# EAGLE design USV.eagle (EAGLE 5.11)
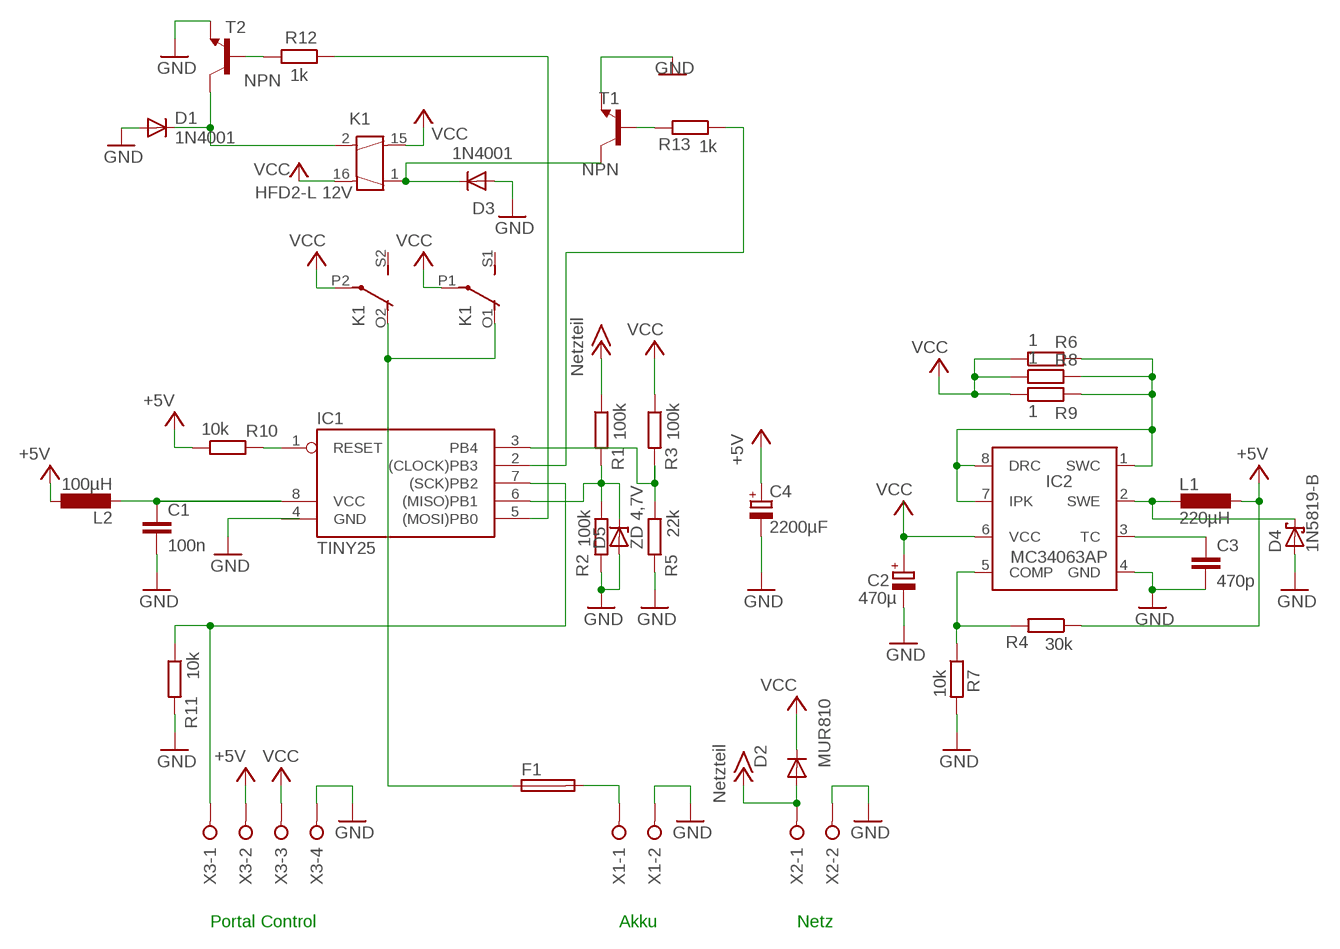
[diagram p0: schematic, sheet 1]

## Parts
C1  100n  C-EU025-025X050  [C025-025X050]
C2  470µ  CPOL-EUE5-10.5  [E5-10,5]
C3  470p  C-EU025-025X050  [C025-025X050]
C4  2200µF  CPOL-EUE5-13  [E5-13]
D1  1N4001  1N4004  [DO41-10]
D2  MUR810  [TO220ACS]
D3  1N4001  1N4004  [DO41-10]
D4  1N5819-B  [DO41-7.6]
D5  ZD 4,7V  ZENER-DIODEZD-2.5  [ZDIO-2.5]
F1  FUSEKS9V  [KS9V]
IC1  TINY25  TINY22P  [DIL08]
IC2  MC34063AP  [DIL-08]
K1  HFD2-L 12V  DS2-L2-12V  [DS2E-L2]
L1  220µH  L-EU6000-XXX-RC  [6000-XXXX-RC]
L2  100µH  L-EU0207/7  [0207/7]
R1  100k  R-EU_0207/10  [0207/10]
R2  100k  R-EU_0207/10  [0207/10]
R3  100k  R-EU_0207/10  [0207/10]
R4  30k  R-EU_0207/10  [0207/10]
R5  22k  R-EU_0207/10  [0207/10]
R6  1  R-EU_0207/10  [0207/10]
R7  10k  R-EU_0207/10  [0207/10]
R8  1  R-EU_0207/10  [0207/10]
R9  1  R-EU_0207/10  [0207/10]
R10  10k  R-EU_0207/7  [0207/7]
R11  10k  R-EU_0207/2V  [0207/2V]
R12  1k  R-EU_0207/2V  [0207/2V]
R13  1k  R-EU_0207/10  [0207/10]
T1  NPN  BC337-16-NPN-TO92-CBE  [TO92-CBE]
T2  NPN  BC337-16-NPN-TO92-CBE  [TO92-CBE]
X1  W237-02P  [W237-132]
X2  W237-02P  [W237-132]
X3  W237-04P  [W237-4P]

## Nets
+5V: C4.+ L1.1 L2.1 R4.1 R10.1 X3.2
+15V: D2.A R1.1 X2.1 ; supply symbol labelled Netzteil
GND: C1.2 C2.- C3.2 C4.- D1.A D3.A D4.A D5.A IC2.4(GND) R2.2 R5.2 R7.2 R11.2 T1.E T2.E X1.2 X2.2 X3.4
N$1: F1.1 K1.O1(2:O) K1.O2(3:O)
N$2: D5.C IC1.6((MISO)PB1) R1.2 R2.1
N$3: IC1.5((MOSI)PB0) R12.1
N$4: IC1.3(PB4) R3.2 R5.1
N$5: D4.C IC2.2(SWE) L1.2
N$6: IC2.1(SWC) IC2.7(IPK) IC2.8(DRC) R6.2 R8.2 R9.2
N$7: IC1.7((SCK)PB2) R11.1 X3.1
N$8: IC1.2((CLOCK)PB3) R13.1
N$9: IC2.5(COMP) R4.2 R7.1
N$10: F1.2 X1.1
N$11: C3.1 IC2.3(TC)
N$12: D1.C K1.2 T2.C
N$13: C1.1 IC1.8(VCC) L2.2
N$14: IC1.1(RESET) R10.2
N$18: D3.C K1.1 T1.C
N$19: R12.2 T2.B
N$20: R13.2 T1.B
VCC: C2.+ D2.C IC2.6(VCC) K1.15 K1.16 K1.P1(2:P) K1.P2(3:P) R3.1 R6.1 R8.1 R9.1 X3.3
Unconnected: K1.S1(2:S) K1.S2(3:S)

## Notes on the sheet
- Portal Control | Akku | Netz

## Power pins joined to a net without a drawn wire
GND: IC1.4(GND)

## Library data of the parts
C1 C3 = rcl:C-EU: CAPACITOR, European symbol
C2 C4 = rcl:CPOL-EU: POLARIZED CAPACITOR, European symbol
D1 D3 = diode:1N4004: DIODE
D2 = diode:MUR810: DIODE
D4 = diode:1N581*: 1.0A SCHOTTKY BARRIER RECTIFIER
D5 = diode:ZENER-DIODE: Z-Diode
F1 = fuse:FUSE: Fuse; OC_FARNELL: unknown; OC_NEWARK: unknown
IC1 = avr-7:TINY22: MICROCONTROLLER 1K ROM 128 bytes RAM 128 bytes EEPROM
IC2 = v-reg-3:MC34063A: 1.5A Step-Up/Down/Inverting Switching Regulator NPN Darlington Switch, Vin 3V to 40V, Current Limiter Input, adjustable Frequency up to 100kHz
K1 = relay:DS2-L2-*: RELAY NAiS bistable, 2 x switch, 4 A/250 V; OC_FARNELL: unknown; OC_NEWARK: unknown
L1 L2 = rcl:L-EU: INDUCTOR, European symbol
R1-R13 = rcl:R-EU_: RESISTOR, European symbol
T1 T2 = transistor:*-NPN-: NPN Transistror BF959 corrected 2008.03.06
X1 X2 = con-wago-508:W237-02P: WAGO SREW CLAMP; OC_FARNELL: unknown; OC_NEWARK: unknown
X3 = con-wago-508:W237-04P: WAGO SREW CLAMP; OC_FARNELL: unknown; OC_NEWARK: unknown

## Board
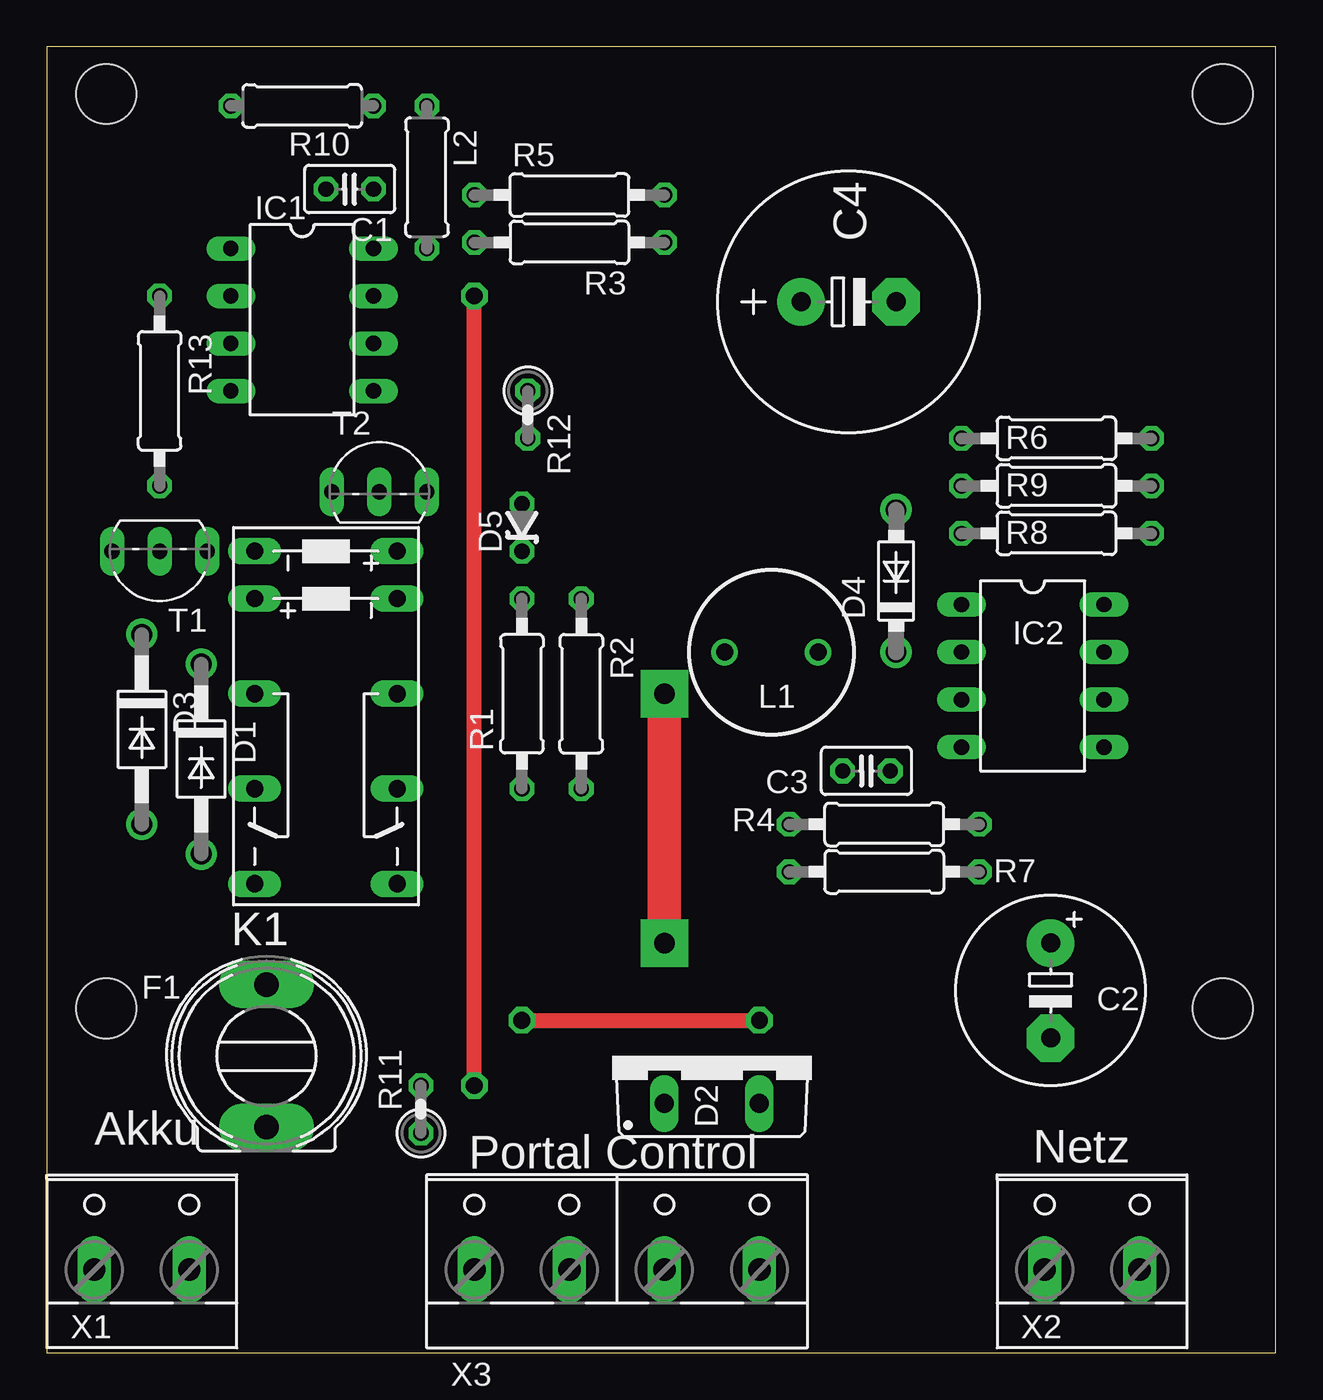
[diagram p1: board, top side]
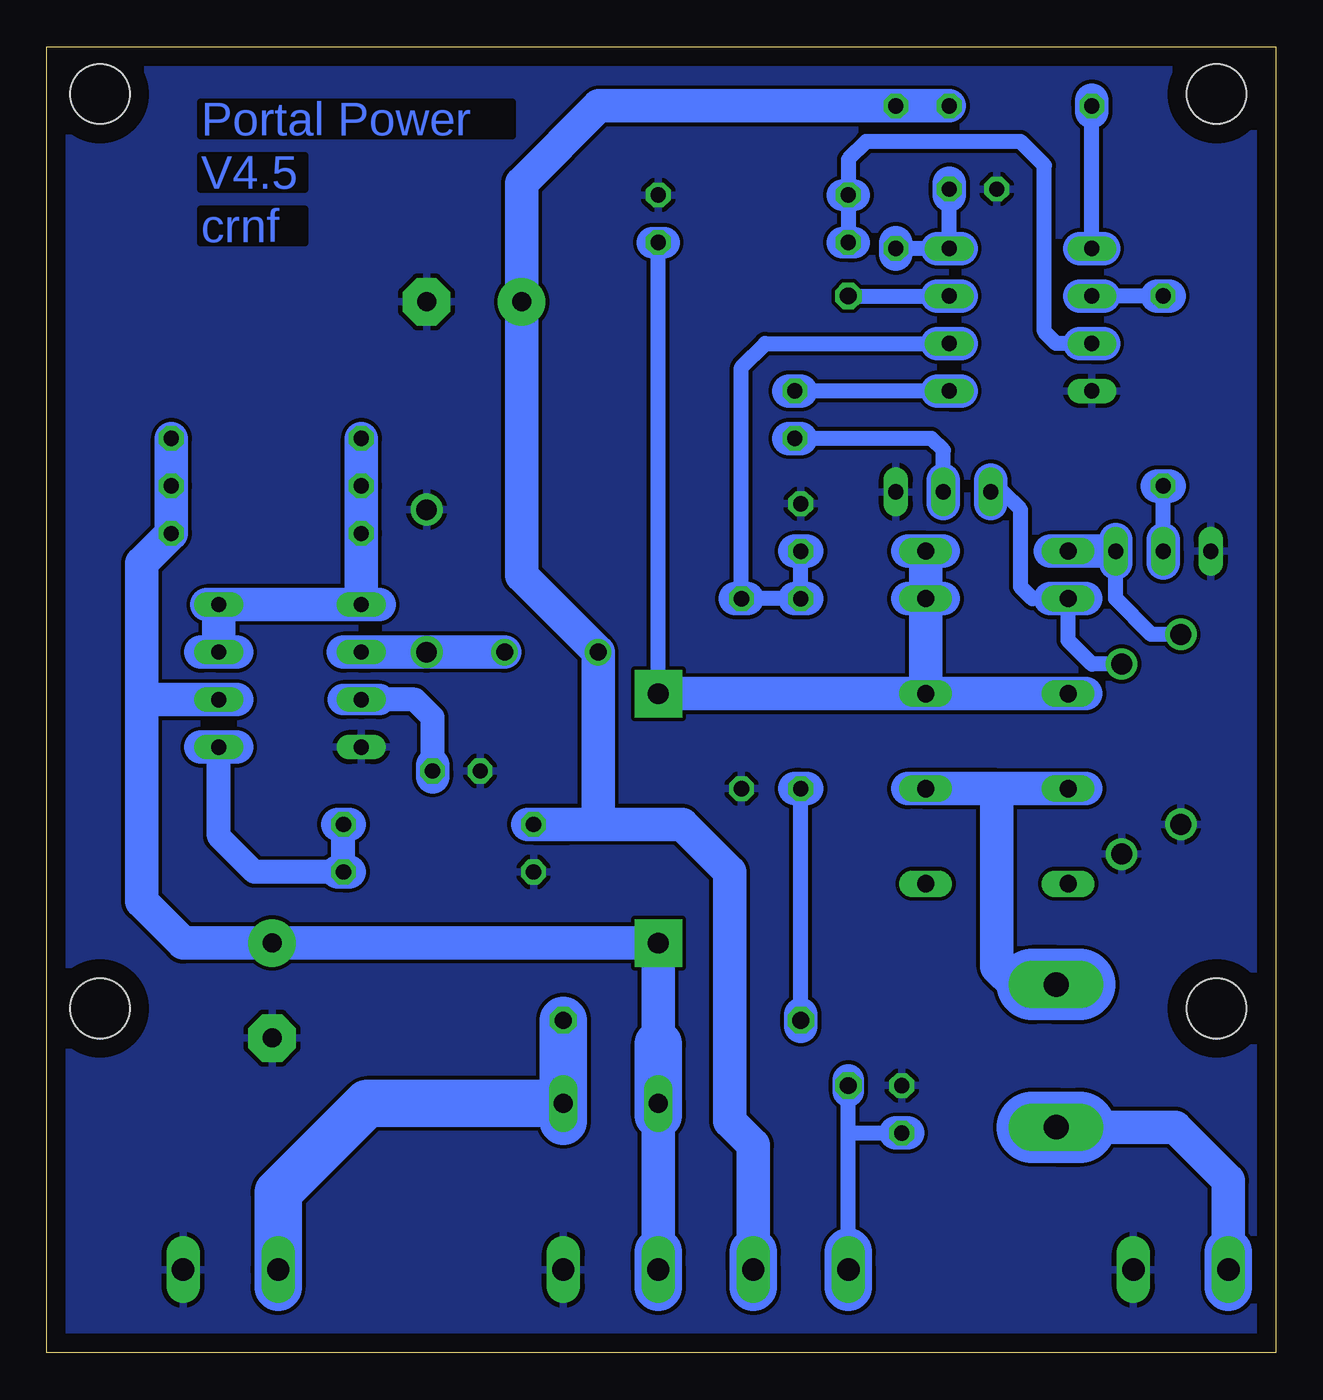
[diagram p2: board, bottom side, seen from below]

Size 65.71 x 69.84 mm. Coordinates in mm from the lower left corner, seen from the top.
Outline: 0,0 65.71,0 65.71,69.84 0,69.84 0,0
Copper layers (1*16): Top 0.035mm / dielectric 1.5mm / Bottom 0.035mm
Design rules "default": minimum track width 10mil, minimum drill 24mil, track to track 8mil, track to pad 8mil, pad to pad 8mil, via to via 8mil, smd to smd 8mil, copper to edge 40mil, drill to drill 8mil, minimum pad ring 10mil, minimum via ring 8mil, stop-mask expansion 4mil, vias tented up to drill 0mil, thermal gap 10mil
Holes 3.2 mm at 3.17,18.41 62.87,18.41 3.17,67.31 62.87,67.31

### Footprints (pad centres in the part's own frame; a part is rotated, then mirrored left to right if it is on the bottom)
C025-025X050 = drill 0.813 octagon: 1 -1.27,0; 2 1.27,0
E5-10,5 = drill 1.016 pad 2.54 round: + -2.54,0 | drill 1.016 pad 2.54 octagon: - 2.54,0
E5-13 = drill 1.016 pad 2.54 round: + -2.54,0 | drill 1.016 pad 2.54 octagon: - 2.54,0
DO41-10 = drill 1.118 round: A 5.08,0; C -5.08,0
TO220ACS = drill 1.016 long: A 2.54,-2.54; C -2.54,-2.54
DO41-7.6 = drill 1.1 pad 1.7 round: A 3.81,0; C -3.81,0
ZDIO-2.5 = drill 0.813 octagon: A 1.27,0; C -1.27,0
KS9V = drill 1.321 pad 2.54 long: 1 0,3.81; 2 0,-3.81
DIL08 = drill 0.813 long: 1 -3.81,-3.81; 2 -1.27,-3.81; 3 1.27,-3.81; 4 3.81,-3.81; 5 3.81,3.81; 6 1.27,3.81; 7 -1.27,3.81; 8 -3.81,3.81
DIL-08 = drill 0.813 long: 1 -3.81,-3.81; 2 -1.27,-3.81; 3 1.27,-3.81; 4 3.81,-3.81; 5 3.81,3.81; 6 1.27,3.81; 7 -1.27,3.81; 8 -3.81,3.81
DS2E-L2 = drill 0.914 long: 1 -7.62,-3.81; 2 -5.08,-3.81; 15 -5.08,3.81; 16 -7.62,3.81; O1 5.08,-3.81; O2 5.08,3.81; P1 0,-3.81; P2 0,3.81; S1 10.16,-3.81; S2 10.16,3.81
6000-XXXX-RC = drill 0.9 pad 1.422 round: 1 -2.5,0; 2 2.5,0
0207/7 = drill 0.813 octagon: 1 -3.81,0; 2 3.81,0
0207/10 = drill 0.813 octagon: 1 -5.08,0; 2 5.08,0
0207/2V = drill 0.813 octagon: 1 -1.27,0; 2 1.27,0
TO92-CBE = drill 0.813 long: B 0,0; C -2.54,0; E 2.54,0
W237-132 = drill 1.194 long: 1 -2.54,-0.635; 2 2.54,-0.635
W237-4P = drill 1.194 long: 1 -7.62,-0.635; 2 -2.54,-0.635; 3 2.54,-0.635; 4 7.62,-0.635

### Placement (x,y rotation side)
C1  16.19,62.23 180 top
C2  53.66,19.37 270 top
C3  43.81,31.11 180 top
C4  42.86,56.2 0 top
D1  8.26,31.75 270 top
D2  35.56,15.88 0 top
D3  5.08,33.34 270 top
D4  45.4,41.27 90 top
D5  25.4,44.13 90 top
F1  11.75,15.88 0 top
IC1  13.65,55.24 270 top
IC2  52.7,36.2 270 top
K1  14.92,35.24 270 top
L1  38.73,37.47 0 top
L2  20.32,62.87 270 top
R1  25.4,35.24 90 top
R2  28.57,35.24 270 top
R3  27.94,59.37 180 top
R4  44.77,28.26 0 top
R5  27.94,61.91 0 top
R6  53.98,48.9 180 top
R7  44.77,25.72 180 top
R8  53.98,43.81 180 top
R9  53.98,46.35 180 top
R10  13.65,66.67 180 top
R11  20,13.02 90 top
R12  25.72,50.16 270 top
R13  6.03,51.44 270 top
T1  6.03,42.86 180 top
T2  17.78,46.04 0 top
X1  5.08,5.08 0 top
X2  55.88,5.08 0 top
X3  30.48,5.08 0 top

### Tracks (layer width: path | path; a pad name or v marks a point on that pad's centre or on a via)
+5V
  Bottom 1.778: 37.78,28.26 R4.1 36.2,28.26 | R10.1 L2.1 36.2,66.67 40.32,62.55 C4.+ 40.32,41.55 L1.1 36.23,28.3 36.2,28.26 | 36.2,28.26 31.75,28.26 29.21,25.72 29.21,12.38 27.94,11.11 27.94,5.4
  Bottom 2.54: 27.94,5.4 X3.2 27.94,3.49
+15V  (via drill 0.9 pad 1.42)
  Top 0.813: v25.4,17.78 v38.1,17.78
  Bottom 0.813: v25.4,17.78 R1.1
  Bottom 1.676: 38.1,18.1 v38.1,17.78 38.1,17.46
  Bottom 1.778: 25.4,18.1 v25.4,17.78 25.4,17.46 | 25.72,30.16 R1.1 25.08,30.16
  Bottom 2.54: 38.1,17.46 v38.1,17.78 D2.A | D2.A 38.1,12.38 | D2.A 48.58,13.34 53.34,8.57 X2.1 53.34,3.49
GND
  pour Bottom: 0,0 0,69.85 66.04,69.85 66.04,0
N$1
  Bottom 1.778: 13.02,19.68 13.97,19.68 14.92,20.64 14.92,30.16 K1.O2 | K1.O2 19.68,30.16 | K1.O2 K1.O1 10.16,30.16
  Bottom 3.81: 10.48,19.68 F1.1 13.02,19.68
N$2
  Bottom 0.813: 18.1,53.98 27.3,53.98 28.57,52.7 R2.1 28.26,40.32 25.72,40.32 | R1.2 D5.C
  Bottom 1.778: 16.83,53.98 IC1.6 18.1,53.98 | 25.72,42.86 D5.C 25.08,42.86 | 25.72,40.32 R1.2 25.08,40.32 | 28.89,40.32 R2.1 28.26,40.32
N$3
  Bottom 0.813: 18.1,51.44 25.4,51.44
  Bottom 1.778: 16.83,51.44 IC1.5 18.1,51.44 | 26.04,51.44 R12.1 25.4,51.44
N$4
  Bottom 0.813: R3.2 R5.1 22.86,63.82 21.91,64.77 13.65,64.77 12.38,63.5 12.38,54.61 11.75,53.98 10.48,53.98
  Bottom 1.676: 23.18,61.91 R5.1 22.54,61.91 | 23.18,59.37 R3.2 22.54,59.37
  Bottom 1.778: 10.48,53.98 IC1.3 9.21,53.98
N$5
  Bottom 1.778: IC2.2 48.58,37.47 | IC2.2 49.85,37.47 | L1.2 D4.C IC2.2
N$6
  Bottom 1.778: IC2.1 R8.2 R9.2 R6.2 | IC2.1 IC2.8 | IC2.8 57.15,40.01 | IC2.7 55.56,37.47 | IC2.7 57.47,37.47 | IC2.8 IC2.7 | 47.94,40.01 IC2.1
N$7  (via drill 0.9 pad 1.42)
  Top 0.813: v22.86,14.29 v22.86,56.52
  Bottom 0.813: 22.86,5.4 22.86,11.75 | 22.86,11.75 22.86,13.97 | 22.86,11.75 20.32,11.75 | v22.86,56.52 18.1,56.52
  Bottom 1.676: 22.86,14.61 v22.86,14.29 22.86,13.97
  Bottom 1.778: 18.1,56.52 IC1.7 16.83,56.52 | 20.32,11.75 R11.1 19.68,11.75
  Bottom 2.54: 22.86,5.4 X3.1 22.86,3.49
N$8
  Bottom 0.813: 5.71,56.52 IC1.2
  Bottom 1.778: 10.48,56.52 IC1.2 9.21,56.52 | 6.35,56.52 R13.1 5.71,56.52
N$9
  Bottom 1.27: IC2.5 56.52,27.62 54.61,25.72 50.16,25.72 | R7.1 R4.2
  Bottom 1.778: 50.16,28.26 R4.2 49.53,28.26 | 50.16,25.72 R7.1 49.53,25.72
N$10
  Bottom 1.778: F1.2 5.4,12.06 2.54,9.21 2.54,5.4
  Bottom 2.54: 2.54,5.4 X1.1 2.54,3.49
  Bottom 3.81: 13.02,12.06 F1.2 10.48,12.06
N$11
  Bottom 1.27: 47.94,34.92 46.04,34.92 45.09,33.97 45.09,31.43
  Bottom 1.676: 49.85,34.92 IC2.3 47.94,34.92
  Bottom 1.778: 45.09,31.43 C3.1 45.09,30.8
N$12
  Bottom 0.813: 12.06,40.32 13.02,40.32 13.65,40.96 13.65,45.09 14.61,46.04 T2.C | D1.C 9.84,36.83 11.11,38.1 K1.2
  Bottom 1.778: 12.06,40.32 K1.2 10.16,40.32 | 15.24,46.67 T2.C 15.24,45.4
N$13
  Bottom 0.813: 18.1,59.05 L2.2 | IC1.8 17.46,61.91 C1.1
  Bottom 1.778: 18.1,59.05 IC1.8 16.83,59.05 | 20.32,59.37 L2.2 20.32,58.74 | 17.46,62.55 C1.1 17.46,61.91
N$14
  Bottom 0.813: IC1.1 R10.2
  Bottom 1.778: 9.84,66.99 R10.2 9.84,66.36 | 10.48,59.05 IC1.1 9.21,59.05
N$15
  Bottom 1.778: 57.47,32.38 56.83,32.38 55.56,32.38
N$16
  Bottom 1.778: 39.37,28.26 40.01,28.26
N$18
  Bottom 0.813: D3.C 6.67,38.42 8.57,40.32 8.57,42.23
  Bottom 1.778: 12.06,42.86 K1.1 T1.C | 8.57,42.23 T1.C | T1.C 8.57,43.5
N$19
  Bottom 0.813: R12.2 25.4,48.9 18.41,48.9 17.78,48.26 17.78,46.67
  Bottom 1.778: 17.78,45.4 T2.B 17.78,46.67 | 26.04,48.9 R12.2 25.4,48.9
N$20
  Bottom 0.813: 6.03,43.5 R13.2
  Bottom 1.778: 6.03,43.5 T1.B 6.03,42.23 | 6.35,46.35 R13.2 5.71,46.35
VCC  (via drill 1.1 pad 2.54)
  Top 1.778: v33.02,21.91 v33.02,35.24
  Bottom 0.813: v33.02,35.24 R3.1
  Bottom 1.676: 33.34,59.37 R3.1 32.7,59.37
  Bottom 1.778: D2.C 33.02,21.59 | 33.02,21.59 v33.02,21.91 | 33.02,21.59 33.34,21.91 C2.+ 58.42,21.91 60.64,24.13 60.64,34.92 | R6.1 R9.1 R8.1 60.64,42.23 60.64,34.92 | 55.56,34.92 IC2.6 60.64,34.92 | 33.02,5.4 33.02,12.7 | K1.15 K1.16 | K1.P2 K1.15 | K1.P2 19.68,35.24 | K1.16 17.78,42.86 | K1.15 17.78,40.32 | K1.15 19.68,40.32 | v33.02,35.24 K1.P2 | K1.16 19.68,42.86 | K1.P2 K1.P1 10.16,35.24
  Bottom 2.54: 33.02,16.51 D2.C 33.02,12.7 | 33.02,5.4 X3.3 33.02,3.49

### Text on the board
Bottom: Portal Power | V4.5 | crnf
tNames: Akku | Portal Control | Netz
